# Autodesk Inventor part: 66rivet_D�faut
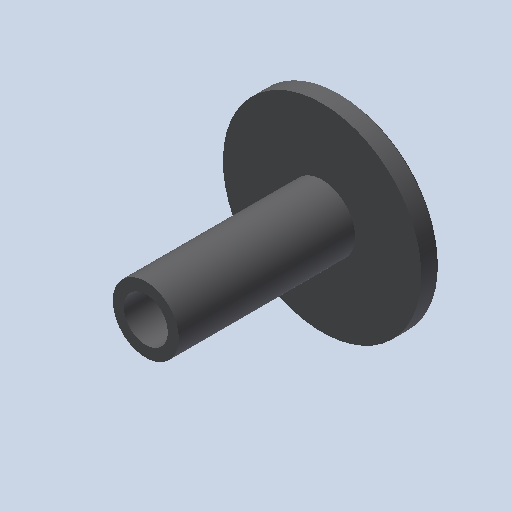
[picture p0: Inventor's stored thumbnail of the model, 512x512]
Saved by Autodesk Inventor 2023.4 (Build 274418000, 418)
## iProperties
Created: 2011-01
Part Number: 66rivet_D�faut
Document SubType Name: Modeling
Designer: eric
Density: 1 g/cm^3
Mass: 0.121913 g
Surface Area: 2.87511 cm^2
Volume: 0.121913 cm^3
Material: Générique
Appearance: Red
Author: eric
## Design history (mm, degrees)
feature "Base1"
node "Corps solides"
node "Corps surfaciques"
node "Solide1"
